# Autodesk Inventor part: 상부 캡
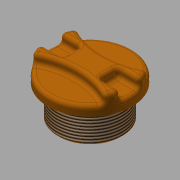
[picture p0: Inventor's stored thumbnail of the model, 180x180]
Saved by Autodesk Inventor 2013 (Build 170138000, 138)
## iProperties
Created: 2016-09
Part Number: 상부 캡
Material: PC/ABS 플라스틱
Document SubType Name: Modeling
Designer: mduedu
Density: 1.493 g/cm^3
Mass: 32.6938 g
Surface Area: 67.9045 cm^2
Volume: 21.8981 cm^3
Author: mduedu
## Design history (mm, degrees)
sketch "스케치1"
  geometry: C1 r 22.5 at (0, 0); 1 further point
  constraints: 1 centre point, 1 coincident
  dimensions: "d0" = 45 diameter of C1
extrude "돌출1" new body sketch "스케치1" distance "d1" = 10; taper "d2" = 0 deg
sketch "스케치2" dims "d4" = 80
  geometry: C1 r 22.5 at (0, 0) reference; 3 further points
  constraints: 3 vertical alignment, 2 other
  dimensions: "d3" = 7 distance of point (0, 7) point (0, 0)
extrude "돌출2" cut sketch "스케치2" distance "d5" = 5; taper "d6" = 0 deg
sketch "스케치3"
  geometry: L1 (-22.5, 0)-(0, 0); L2 (-21.937, 5)-(-10, 5); L3 (-10, 5)-(-10, -5); L4 (-10, -5)-(-21.937, -5); A1 r 22.5 centre (0, 0) between (-19.118, 11.864) and (-19.118, -11.864) reference; A2 r 22.5 centre (0, 0) between (-21.937, 5) and (-21.937, -5); 1 further point
  constraints: 8 end point, 5 point on circle, 2 horizontal, 1 centre point, 1 coincident, 1 parallel, 1 perpendicular, 1 symmetric about line
  dimensions: "d7" = 10 distance from line of L3 point (0, 0); "d8" = 10 distance of L2.end L3.end
extrude "돌출3" cut sketch "스케치3" distance "d9" = 5; taper "d10" = 0 deg
fillet "모깎기1" dims "d11" = 2
fillet "모깎기2" dims "d12" = 2
fillet "모깎기3" dims "d13" = 2
sketch "스케치4"
  geometry: C1 r 17.5 at (0, 0); 1 further point
  constraints: 1 centre point, 1 coincident
  dimensions: "d14" = 35 diameter of C1
extrude "돌출4" join sketch "스케치4" distance "d15" = 17; taper "d16" = 0 deg
sketch "스케치5"
  geometry: C1 r 12.5 at (0, 0); 1 further point
  constraints: 1 centre point, 1 coincident
  dimensions: "d17" = 25 diameter of C1
extrude "돌출5" cut sketch "스케치5" distance "d18" = 10; taper "d19" = 0 deg
fillet "모깎기4" dims "d20" = 3
feature "스레드1" dims "d21" = 10, "d22" = 0
chamfer "모따기1" distance "d23" = 1; stored, may be unused: second distance "d24" = 2, angle "d25" = 45 deg
node "솔리드1"
mirror "대칭1"
mirror "대칭2"
node "투영된 루프1"
